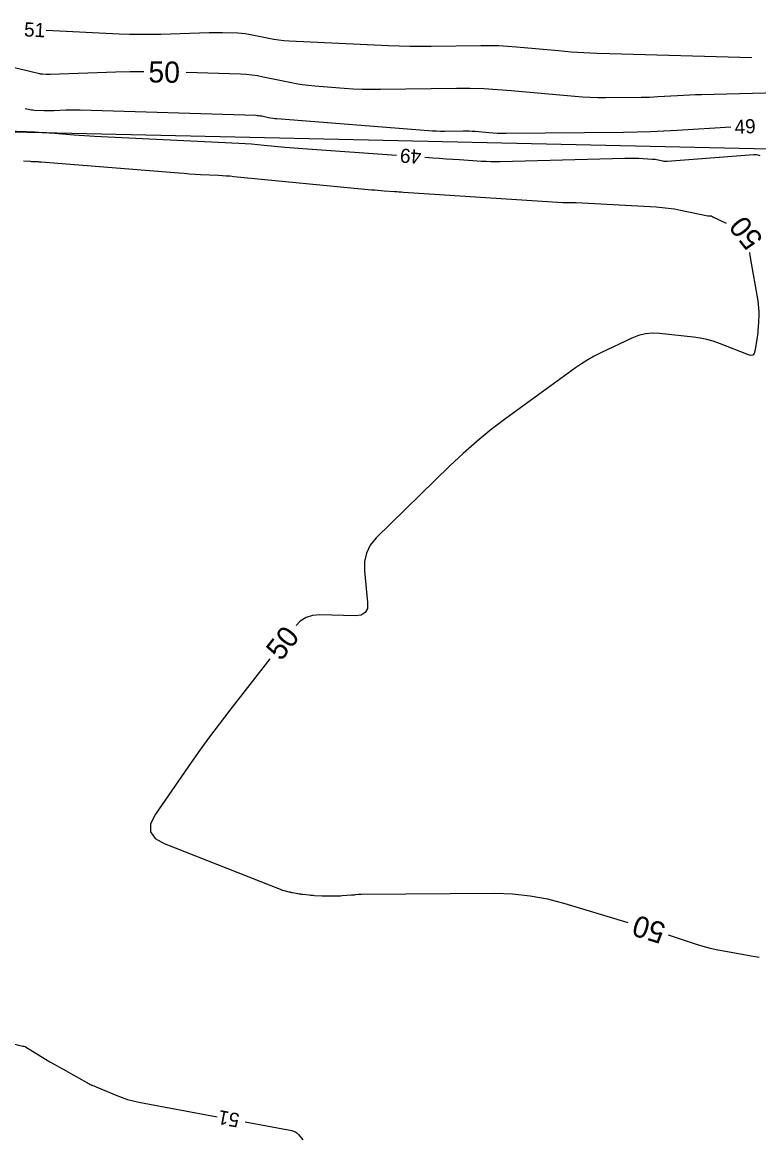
# Model space of a CAD drawing. Extents: x 2384780 to 2405861, y 547869 to 573706.
# Drawn here: x 2391960.1 to 2392064.2, y 552437.4 to 552594.8 of the extents above; entities that cross this region are included whole.
import ezdxf

# ---------------------------------------------------------------- set-up
doc = ezdxf.new("R2010")
doc.units = 0
for name, color, linetype in [('Old_Level_5', 7, 'Continuous'), ('Old_Level_60', 7, 'Continuous'), ('Old_Level_61', 7, 'Continuous')]:
    doc.layers.add(name, color=color, linetype=linetype)

msp = doc.modelspace()

# ---------------------------------------------------------------- linework, layer by layer
at = {"layer": 'Old_Level_5'}
msp.add_line((2392210.721, 552573.62725), (2391913.02425, 552580.30675), dxfattribs=at)
at = {"layer": 'Old_Level_60'}
for points in [[(2392063.272, 552589.80475), (2392043.13225, 552590.33025), (2392041.31775, 552590.3925), (2392039.50475, 552590.4845), (2392037.69375, 552590.6065), (2392035.88425, 552590.758), (2392029.97675, 552591.30225), (2392028.71, 552591.402), (2392027.44225, 552591.4685), (2392026.173, 552591.50175), (2392024.9025, 552591.5015), (2392017.88925, 552591.40825), (2392016.3865, 552591.3995), (2392014.88425, 552591.413), (2392013.38225, 552591.44875), (2392011.88075, 552591.507), (2391997.801, 552592.1585), (2391997.0745, 552592.20675), (2391996.35175, 552592.28375), (2391995.63275, 552592.39), (2391994.91725, 552592.52525), (2391992.5865, 552593.0145), (2391992.08575, 552593.10825), (2391991.58225, 552593.1795), (2391991.07625, 552593.2285), (2391990.5675, 552593.255), (2391988.3755, 552593.32125), (2391987.90575, 552593.33175), (2391987.436, 552593.335), (2391986.9665, 552593.331), (2391986.49675, 552593.3195), (2391979.636, 552593.0995), (2391978.16575, 552593.0675), (2391976.696, 552593.06575), (2391975.2265, 552593.094), (2391973.7575, 552593.1525), (2391963.45425, 552593.669)], [(2392060.29725, 552579.96575), (2392052.703, 552579.513), (2392050.80725, 552579.412), (2392048.91075, 552579.33425), (2392047.01325, 552579.28), (2392045.115, 552579.24925), (2392028.48775, 552579.08325), (2392027.88175, 552579.085), (2392027.27625, 552579.102), (2392026.6715, 552579.1345), (2392026.06725, 552579.1825), (2392024.09475, 552579.36425), (2392023.67175, 552579.3975), (2392023.2485, 552579.41975), (2392022.8245, 552579.43075), (2392022.40025, 552579.43075), (2392019.77125, 552579.39575), (2392019.208, 552579.39475), (2392018.64525, 552579.4065), (2392018.08275, 552579.43125), (2392017.521, 552579.46875), (2391996.08625, 552581.14475), (2391995.78475, 552581.17325), (2391995.4845, 552581.2115), (2391995.1855, 552581.25925), (2391994.88825, 552581.31675), (2391993.91875, 552581.52), (2391993.7105, 552581.559), (2391993.501, 552581.58875), (2391993.2905, 552581.609), (2391993.079, 552581.62025), (2391968.2595, 552582.3705), (2391967.751, 552582.382), (2391967.2425, 552582.38525), (2391966.734, 552582.381), (2391966.2255, 552582.3685), (2391964.5645, 552582.31525), (2391964.20875, 552582.30675), (2391963.85275, 552582.30375), (2391963.49675, 552582.3065), (2391963.141, 552582.31475), (2391961.73975, 552582.35875), (2391961.541, 552582.37025), (2391961.3435, 552582.39175), (2391961.14725, 552582.4235), (2391960.9525, 552582.4655), (2391960.475, 552582.5815)], [(2391941.67225, 552580.226), (2391960.29725, 552579.3785), (2391960.67275, 552579.36125), (2391961.04825, 552579.34375), (2391961.42375, 552579.326), (2391961.799, 552579.30775), (2391963.0255, 552579.2485), (2391963.28825, 552579.23475), (2391963.55075, 552579.219), (2391963.81325, 552579.201), (2391964.07575, 552579.181), (2391967.40575, 552578.9135), (2391968.11975, 552578.859), (2391968.83375, 552578.81), (2391969.54825, 552578.7665), (2391970.26325, 552578.7285), (2391990.694, 552577.72075), (2391991.5925, 552577.67125), (2391992.4905, 552577.611), (2391993.38775, 552577.54025), (2391994.284, 552577.45875), (2391997.211, 552577.1755), (2391997.83825, 552577.11675), (2391998.466, 552577.062), (2391999.094, 552577.0115), (2391999.7225, 552576.96475), (2392013.0015, 552576.02225)], [(2392016.9915, 552575.739), (2392018.142, 552575.6575), (2392019.0875, 552575.591), (2392020.03325, 552575.526), (2392020.979, 552575.46225), (2392021.92475, 552575.40025), (2392025.01475, 552575.19925), (2392025.677, 552575.16375), (2392026.3395, 552575.1435), (2392027.0025, 552575.13825), (2392027.66575, 552575.14825), (2392045.311, 552575.617), (2392045.80225, 552575.625), (2392046.2935, 552575.623), (2392046.78475, 552575.61075), (2392047.2755, 552575.58875), (2392049.138, 552575.4855), (2392049.35175, 552575.46975), (2392049.56425, 552575.446), (2392049.776, 552575.414), (2392049.9865, 552575.37425), (2392050.67275, 552575.231), (2392050.82, 552575.2055), (2392050.96825, 552575.19075), (2392051.117, 552575.18625), (2392051.26625, 552575.19225), (2392063.54975, 552576.1135), (2392063.8425, 552576.11175), (2392064.122, 552576.062), (2392064.38825, 552575.964)], [(2391958.99675, 552450.36125), (2391960.1335, 552450.118), (2391960.173, 552450.1095), (2391960.21225, 552450.1005), (2391960.2515, 552450.091), (2391960.2905, 552450.081), (2391960.418, 552450.04825), (2391960.445, 552450.04025), (2391960.471, 552450.03025), (2391960.49625, 552450.0185), (2391960.52075, 552450.0045), (2391963.36175, 552448.26325), (2391963.9725, 552447.8935), (2391964.587, 552447.53), (2391965.2055, 552447.17325), (2391965.8275, 552446.823), (2391969.5235, 552444.768), (2391969.5375, 552444.76), (2391969.5515, 552444.75175), (2391969.565, 552444.74325), (2391969.5785, 552444.73425), (2391969.6225, 552444.70475), (2391969.632, 552444.69875), (2391969.64175, 552444.69325), (2391969.652, 552444.68825), (2391969.66225, 552444.684), (2391969.8235, 552444.6205), (2391969.858, 552444.60675), (2391969.8925, 552444.59275), (2391969.92675, 552444.57875), (2391969.96125, 552444.5645), (2391973.4415, 552443.1085), (2391974.1935, 552442.817), (2391974.95775, 552442.5665), (2391975.73425, 552442.35725), (2391976.523, 552442.18925), (2391987.63775, 552440.1255)], [(2391991.5705, 552439.3955), (2391998.1635, 552438.1715), (2391998.44025, 552438.09625), (2391998.692, 552437.97825), (2391998.91875, 552437.817), (2391999.1205, 552437.61325), (2391999.73875, 552436.87675)]]:
    msp.add_lwpolyline(points, dxfattribs=at)
at = {"layer": 'Old_Level_61'}
for points in [[(2391977.26175, 552587.8115), (2391975.3045, 552587.79425), (2391973.2695, 552587.745), (2391964.0165, 552587.44825), (2391963.8665, 552587.4445), (2391963.71625, 552587.44325), (2391963.56625, 552587.4445), (2391963.416, 552587.448), (2391962.92575, 552587.46325), (2391962.821, 552587.46925), (2391962.717, 552587.48075), (2391962.61375, 552587.4975), (2391962.51125, 552587.5195), (2391958.96825, 552588.3795)], [(2392081.29525, 552585.217), (2392056.113, 552584.56775), (2392055.26625, 552584.54225), (2392054.41975, 552584.50975), (2392053.57375, 552584.47), (2392052.72775, 552584.42325), (2392049.96525, 552584.2585), (2392049.373, 552584.227), (2392048.78075, 552584.20275), (2392048.188, 552584.18575), (2392047.59525, 552584.17625), (2392042.5445, 552584.12575), (2392041.46275, 552584.12875), (2392040.382, 552584.15925), (2392039.3025, 552584.21725), (2392038.22425, 552584.30275), (2392029.21025, 552585.133), (2392027.2775, 552585.28525), (2392025.343, 552585.38675), (2392023.4065, 552585.4375), (2392021.46775, 552585.437), (2392010.71025, 552585.294), (2392009.4315, 552585.2915), (2392008.15375, 552585.31825), (2392006.877, 552585.37425), (2392005.601, 552585.45925), (2392001.43475, 552585.78525), (2392000.544, 552585.86925), (2391999.65725, 552585.98175), (2391998.77475, 552586.123), (2391997.89625, 552586.29275), (2391994.15075, 552587.07875), (2391993.346, 552587.22925), (2391992.537, 552587.344), (2391991.7235, 552587.4225), (2391990.906, 552587.46525), (2391983.2605, 552587.6965)], [(2391960.223, 552575.20925), (2391961.232, 552575.16325), (2391961.37875, 552575.1565), (2391961.52575, 552575.14975), (2391961.6725, 552575.14275), (2391961.81925, 552575.13575), (2391962.2985, 552575.1125), (2391962.40125, 552575.10725), (2391962.504, 552575.101), (2391962.6065, 552575.094), (2391962.709, 552575.086), (2391982.18025, 552573.5225), (2391982.95625, 552573.46325), (2391983.73275, 552573.41), (2391984.5095, 552573.3625), (2391985.28675, 552573.32125), (2391987.82625, 552573.196), (2391988.37, 552573.166), (2391988.9135, 552573.1295), (2391989.4565, 552573.08675), (2391989.999, 552573.0375), (2392009.472, 552571.1525), (2392009.91725, 552571.11075), (2392010.363, 552571.072), (2392010.80875, 552571.036), (2392011.255, 552571.003), (2392012.7125, 552570.8995), (2392013.025, 552570.8775), (2392013.3375, 552570.856), (2392013.64975, 552570.835), (2392013.96225, 552570.8145), (2392036.51325, 552569.34825), (2392036.699, 552569.33825), (2392036.88475, 552569.3325), (2392037.07075, 552569.331), (2392037.2565, 552569.334), (2392037.864, 552569.35), (2392037.99425, 552569.35225), (2392038.1245, 552569.35175), (2392038.2545, 552569.3485), (2392038.3845, 552569.3425), (2392049.6995, 552568.716), (2392050.56925, 552568.6515), (2392051.43475, 552568.5545), (2392052.296, 552568.425), (2392053.15325, 552568.26275), (2392057.04425, 552567.451), (2392057.0935, 552567.4425), (2392057.14325, 552567.4375), (2392057.193, 552567.436), (2392057.243, 552567.438), (2392057.4065, 552567.45025), (2392057.44075, 552567.45), (2392057.47375, 552567.44425), (2392057.505, 552567.43275), (2392057.53475, 552567.4155), (2392057.6305, 552567.3495), (2392057.6515, 552567.33575), (2392057.67275, 552567.323), (2392057.69475, 552567.31125), (2392057.717, 552567.3005), (2392059.6235, 552566.429)], [(2392062.90475, 552562.26525), (2392062.91425, 552562.17225), (2392062.95325, 552561.8765), (2392063.001, 552561.582), (2392064.088, 552555.42375), (2392064.1635, 552554.915), (2392064.21075, 552554.4045), (2392064.22975, 552553.892), (2392064.2205, 552553.37775), (2392064.144, 552551.69475), (2392064.1225, 552551.33475), (2392064.091, 552550.9755), (2392064.04925, 552550.6175), (2392063.99725, 552550.2605), (2392063.68725, 552548.32475), (2392063.58, 552547.98075), (2392063.39175, 552547.779), (2392063.1225, 552547.71925), (2392062.77175, 552547.80125), (2392058.6635, 552549.40925), (2392057.77575, 552549.724), (2392056.87325, 552549.97875), (2392055.956, 552550.1735), (2392055.02375, 552550.3085), (2392050.21325, 552550.8465), (2392049.1945, 552550.89125), (2392048.19925, 552550.7955), (2392047.22775, 552550.559), (2392046.28025, 552550.182), (2392041.884, 552548.07975), (2392040.95425, 552547.60875), (2392040.0485, 552547.09725), (2392039.16725, 552546.54475), (2392038.3105, 552545.95125), (2392028.4735, 552538.805), (2392026.39625, 552537.23725), (2392024.38025, 552535.597), (2392022.42575, 552533.88425), (2392020.53225, 552532.09875), (2392010.1255, 552521.92075), (2392009.284, 552520.90975), (2392008.7235, 552519.797), (2392008.444, 552518.583), (2392008.4455, 552517.2675), (2392008.9095, 552512.8045), (2392008.87625, 552511.9705), (2392008.578, 552511.381), (2392008.01425, 552511.036), (2392007.18575, 552510.93575), (2392002.15575, 552511.0505), (2392001.1295, 552510.966), (2392000.2065, 552510.66325), (2391999.3865, 552510.14225), (2391998.808, 552509.5455)], [(2391995.091, 552504.837), (2391989.40825, 552497.587), (2391987.8865, 552495.615), (2391986.395, 552493.621), (2391984.93375, 552491.6045), (2391983.50275, 552489.56575), (2391978.87725, 552482.86975), (2391978.213, 552481.5345), (2391978.20225, 552480.3985), (2391978.845, 552479.462), (2391980.14125, 552478.72475), (2391996.5575, 552472.2755), (2391996.72175, 552472.214), (2391996.88775, 552472.15775), (2391997.05525, 552472.1065), (2391997.2245, 552472.06075), (2391997.78025, 552471.91975), (2391997.8995, 552471.8905), (2391998.01925, 552471.8635), (2391998.1395, 552471.8385), (2391998.26025, 552471.81575), (2391999.05325, 552471.673), (2391999.22325, 552471.64375), (2391999.39375, 552471.61725), (2391999.56475, 552471.5935), (2391999.736, 552471.5725), (2392000.62675, 552471.47075), (2392000.81775, 552471.45025), (2392001.009, 552471.433), (2392001.2005, 552471.4185), (2392001.392, 552471.40725), (2392002.406, 552471.35475), (2392002.62325, 552471.345), (2392002.8405, 552471.3385), (2392003.058, 552471.33525), (2392003.2755, 552471.33525), (2392004.3675, 552471.3425), (2392004.60125, 552471.346), (2392004.83525, 552471.353), (2392005.06875, 552471.3635), (2392005.3025, 552471.3775), (2392006.63775, 552471.4685), (2392006.77275, 552471.4785), (2392006.90775, 552471.48975), (2392007.0425, 552471.50275), (2392007.17725, 552471.51725), (2392007.617, 552471.56675), (2392007.71125, 552471.57625), (2392007.80575, 552471.583), (2392007.9005, 552471.5875), (2392007.99525, 552471.58925), (2392026.89475, 552471.70675), (2392029.4115, 552471.6295), (2392031.9015, 552471.366), (2392034.36475, 552470.91625), (2392036.801, 552470.2805), (2392045.7175, 552467.598)], [(2392051.41, 552465.84825), (2392055.25125, 552464.57925), (2392056.305, 552464.25275), (2392057.3685, 552463.96575), (2392058.44175, 552463.71825), (2392059.52525, 552463.5105), (2392063.43675, 552462.83425), (2392064.2755, 552462.6915)]]:
    msp.add_lwpolyline(points, dxfattribs=at)

# ---------------------------------------------------------------- texts
at = {"layer": 'Old_Level_60'}
for s, rotation, p in [('51', 357.0565694, (2391960.27325, 552592.82875)), ('49', 2.9227222, (2392060.86675, 552579.00725)), ('49', 175.9400917, (2392016.54375, 552576.77325)), ('51', 169.4823389, (2391990.90125, 552440.53675))]:
    msp.add_text(s, height=2, rotation=rotation, dxfattribs=at).set_placement(p)
at = {"layer": 'Old_Level_61'}
for rotation, p in [(358.902325, (2391977.87125, 552586.32375)), (128.2393833, (2392064.9615, 552564.20175)), (51.7109917, (2391996.6555, 552504.41475)), (162.9118333, (2392051.2485, 552467.371))]:
    msp.add_text('50', height=3, rotation=rotation, dxfattribs=at).set_placement(p)

doc.saveas('drawing.dxf')
